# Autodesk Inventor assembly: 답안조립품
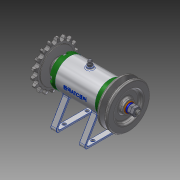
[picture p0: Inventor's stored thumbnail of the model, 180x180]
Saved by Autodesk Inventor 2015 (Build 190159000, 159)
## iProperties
Created: 2016-03
Part Number: 답안조립품
Document SubType Name: Assembly
Designer: Administrator
Author: Administrator
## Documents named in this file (16)
- C:\Users\Administrator\Desktop\460307V1012\답안조립품.iam
- C:\Users\Administrator\Desktop\460307V1012\1본체.ipt
- C:\Users\Administrator\Desktop\460307V1012\축.ipt
- C:\Users\Administrator\Desktop\460307V1012\키 3 x 3 x 12.ipt
- C:\Users\Administrator\Desktop\460307V1012\V벨트풀리.ipt
- C:\Users\Administrator\Desktop\460307V1012\스프로킷.ipt
- C:\Users\Administrator\Desktop\460307V1012\와셔 8x17.ipt
- C:\Users\Administrator\Desktop\460307V1012\스프링와셔 8.ipt
- C:\Users\Administrator\Desktop\460307V1012\너트 M 8.ipt
- C:\Users\Administrator\Desktop\460307V1012\베어링 15 x 32 x 9.ipt
- C:\Users\Administrator\Desktop\460307V1012\커버.ipt
- C:\Users\Administrator\Desktop\460307V1012\오일 실 15 25 7.ipt
- C:\Users\Administrator\Desktop\460307V1012\니플 M 6 x 0.75.ipt
- C:\Users\Administrator\Desktop\460307V1012\와셔 6x11.5.ipt
- C:\Users\Administrator\Desktop\460307V1012\볼트 M 6 x 8.ipt
- C:\Users\Administrator\Desktop\460307V1012\볼트 M4 x 12.ipt
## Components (12 placed, 4 different names)
1. 1본체:1 — 각도:4, 각도:5, 각도:6, 각도:7, 각도:9, 각도:10
2. V벨트풀리:1 — 각도:1
3. KS B 2023 6002 - 15 x 32 x 9:1
4. KS B 2023 6002 - 15 x 32 x 9:2
5. ISO 4762 M4 x 12:1 — 각도:9
6. ISO 4762 M4 x 12:2
7. ISO 4762 M4 x 12:3
8. ISO 4762 M4 x 12:4
9. ISO 4762 M4 x 12:5 — 각도:10
10. ISO 4762 M4 x 12:6
11. ISO 4762 M4 x 12:7
12. ISO 4762 M4 x 12:8
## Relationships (7: Angle 7)
- 각도:1 [Angle]: V벨트풀리:1
- 각도:4 [Angle]: 1본체:1
- 각도:5 [Angle]: 1본체:1
- 각도:6 [Angle]: 1본체:1
- 각도:7 [Angle]: 1본체:1
- 각도:9 [Angle]: 1본체:1 ↔ ISO 4762 M4 x 12:1
- 각도:10 [Angle]: 1본체:1 ↔ ISO 4762 M4 x 12:5
